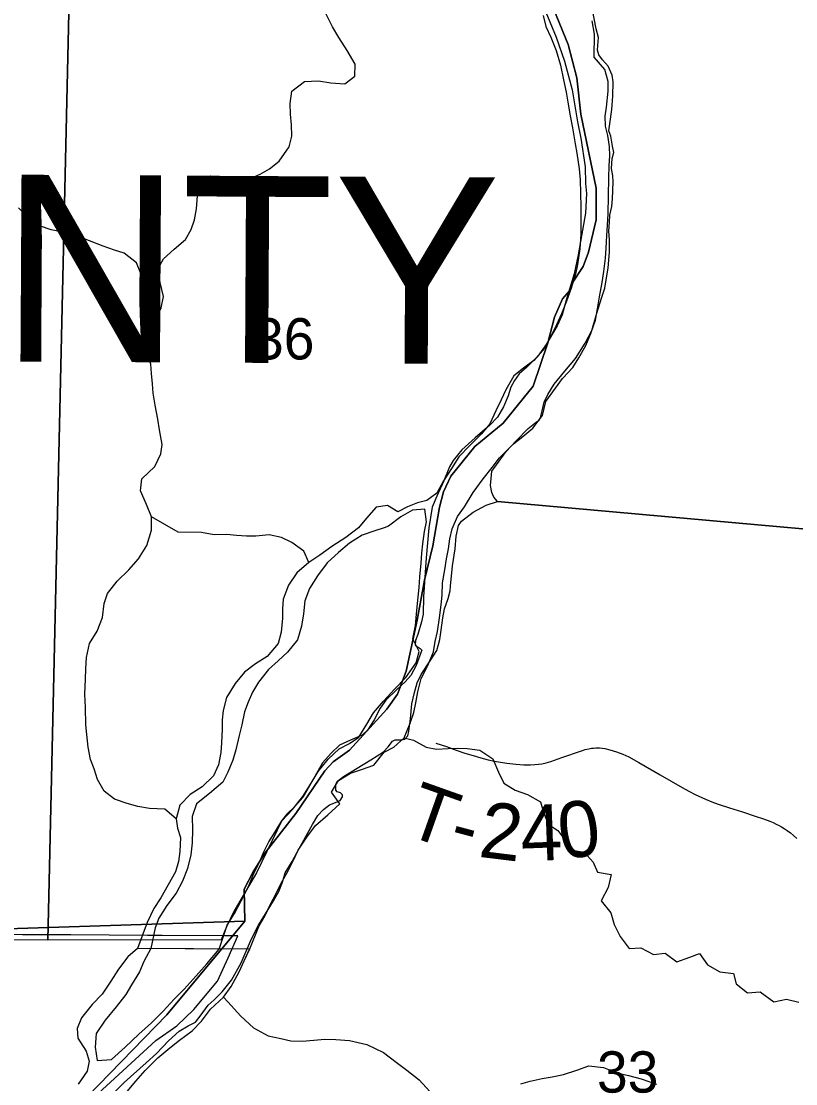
# Model space of a CAD drawing. Extents: x -38.1 to 35.9, y -2.7 to 28.5.
# Drawn here: x 10.189 to 10.974, y 17.716 to 18.793 of the extents above; entities that cross this region are included whole.
import ezdxf

# ---------------------------------------------------------------- set-up
doc = ezdxf.new("R2010")
doc.units = 0
for name, color, linetype in [('GM_X_Major_River_Text', 7, 'Continuous'), ('GM_X_Minor_Lake', 7, 'Continuous'), ('GM_X_Minor_River', 7, 'Continuous'), ('GM_X_Rail_Line', 7, 'Continuous'), ('GM_X_Section', 7, 'Continuous'), ('GM_X_Township_Road', 7, 'Continuous'), ('GM_X_US_Route', 7, 'Continuous')]:
    doc.layers.add(name, color=color, linetype=linetype)

msp = doc.modelspace()

# ---------------------------------------------------------------- linework, layer by layer
at = {"layer": 'GM_X_Major_River_Text'}
msp.add_lwpolyline([(10.6088, 18.0608), (10.6195, 18.0574), (10.6293, 18.0539), (10.6384, 18.0508), (10.6468, 18.0482), (10.6544, 18.0459), (10.662, 18.0441), (10.6684, 18.0427), (10.6745, 18.0415), (10.6807, 18.0405), (10.69, 18.0395), (10.6981, 18.039), (10.7049, 18.039), (10.7092, 18.0392), (10.7129, 18.0395), (10.7163, 18.0399), (10.7206, 18.0409), (10.7253, 18.0423), (10.7365, 18.0462), (10.7564, 18.0532), (10.7603, 18.0545), (10.7638, 18.0552), (10.7668, 18.0558), (10.7688, 18.0559), (10.7709, 18.056), (10.7727, 18.056), (10.7746, 18.056), (10.7774, 18.0557), (10.78, 18.0553), (10.7854, 18.0541), (10.7919, 18.0521), (10.7983, 18.0496), (10.8044, 18.0469), (10.8147, 18.0414), (10.8364, 18.0289), (10.8587, 18.0158), (10.8652, 18.0121), (10.8719, 18.0087), (10.8822, 18.0041), (10.8886, 18.0014), (10.8952, 17.999), (10.9067, 17.9952), (10.9196, 17.9912), (10.9326, 17.987), (10.9409, 17.9842), (10.9474, 17.9818), (10.9507, 17.9804), (10.9538, 17.9789), (10.9568, 17.9774), (10.9594, 17.976), (10.9621, 17.9744), (10.9649, 17.9724), (10.9683, 17.9698), (10.9715, 17.9671), (10.9749, 17.9641)], dxfattribs=at)
at = {"layer": 'GM_X_Section'}
for points in [[(10.3168, 18.4914), (10.3255, 18.4917), (10.3302, 18.5023), (10.3326, 18.5137), (10.3293, 18.5278), (10.3272, 18.5422), (10.3327, 18.552), (10.3434, 18.5618), (10.3549, 18.5715), (10.3607, 18.5817), (10.3642, 18.5916), (10.3663, 18.6025), (10.3672, 18.6158), (10.3693, 18.6287), (10.3803, 18.6362), (10.3924, 18.6341), (10.4053, 18.6306), (10.4174, 18.6319), (10.4308, 18.6379), (10.4403, 18.6431), (10.4499, 18.6509), (10.46, 18.6653), (10.4627, 18.6762), (10.4625, 18.6876), (10.4615, 18.6987), (10.4613, 18.7093), (10.4629, 18.7218), (10.4756, 18.7316), (10.49, 18.7322), (10.5025, 18.7305), (10.5165, 18.7292), (10.5268, 18.737), (10.527, 18.7492), (10.5188, 18.763), (10.5106, 18.7764), (10.5039, 18.7871), (10.4976, 18.8001)], [(10.3455, 17.9843), (10.3342, 17.994), (10.3187, 17.9945), (10.3066, 17.9966), (10.296, 17.9997), (10.2831, 18.0041), (10.2726, 18.0122), (10.2659, 18.024), (10.2623, 18.0347), (10.2586, 18.0443), (10.2565, 18.0568), (10.2551, 18.0697), (10.2541, 18.0796), (10.2535, 18.0971), (10.253, 18.1104), (10.2535, 18.1256), (10.254, 18.1362), (10.2545, 18.1476), (10.2578, 18.162), (10.2655, 18.1744), (10.271, 18.1884), (10.2727, 18.2025), (10.2758, 18.2127), (10.2858, 18.2251), (10.2977, 18.2367), (10.3073, 18.2476), (10.3158, 18.2612), (10.3206, 18.2767), (10.3207, 18.2904), (10.3156, 18.303), (10.3093, 18.3168), (10.3106, 18.3289), (10.324, 18.3413), (10.3299, 18.3541), (10.3315, 18.3636), (10.3286, 18.3784), (10.3269, 18.3895), (10.3244, 18.4036), (10.3223, 18.4158), (10.3216, 18.4253), (10.3206, 18.4355), (10.32, 18.445), (10.3156, 18.4576), (10.3127, 18.4687), (10.3155, 18.4793), (10.3168, 18.4914), (10.3154, 18.5055), (10.3137, 18.5177), (10.3119, 18.5276), (10.3097, 18.5371), (10.3053, 18.5478), (10.2929, 18.5578), (10.2831, 18.5606), (10.2714, 18.5646), (10.2578, 18.57), (10.245, 18.5751), (10.234, 18.5783), (10.2189, 18.5812), (10.2079, 18.5851), (10.1981, 18.5909), (10.1858, 18.6036)], [(10.4802, 18.244), (10.475, 18.2555), (10.463, 18.2644), (10.4525, 18.2694), (10.44, 18.2722), (10.4263, 18.2709), (10.4168, 18.2706), (10.4066, 18.2715), (10.3971, 18.2724), (10.3842, 18.2722), (10.3714, 18.2746), (10.3475, 18.2749), (10.3207, 18.2904)], [(10.5766, 18.0662), (10.5861, 18.0638), (10.5989, 18.0568), (10.6095, 18.0548), (10.6213, 18.0554), (10.6307, 18.0557), (10.6406, 18.0556), (10.6535, 18.0539), (10.6666, 18.045), (10.6722, 18.0316), (10.6777, 18.0202), (10.6894, 18.0132), (10.7018, 18.0089), (10.715, 18.0015), (10.7179, 17.9908), (10.7227, 17.9786), (10.7325, 17.9724), (10.7396, 17.9628), (10.747, 17.9525), (10.7592, 17.9504), (10.7685, 17.9401), (10.7729, 17.9302), (10.7866, 17.9277), (10.7834, 17.9145), (10.7764, 17.9009), (10.7861, 17.889), (10.7897, 17.8772), (10.7957, 17.8649), (10.805, 17.8527), (10.8168, 17.8533), (10.8296, 17.8467), (10.8413, 17.8481), (10.853, 17.8392), (10.8663, 17.844), (10.8762, 17.8476), (10.8844, 17.8362), (10.8969, 17.8292), (10.9105, 17.8275), (10.9134, 17.8168), (10.9247, 17.8076), (10.9376, 17.8086), (10.9515, 17.7985), (10.9644, 17.8014), (10.9769, 17.7982)], [(10.3934, 17.8034), (10.3978, 17.7987), (10.4113, 17.7842), (10.4241, 17.7722), (10.4388, 17.7641), (10.4516, 17.7613), (10.4618, 17.7592), (10.4732, 17.7587), (10.485, 17.7597), (10.4964, 17.7607), (10.5074, 17.7606), (10.5214, 17.7593), (10.5388, 17.7553), (10.5557, 17.7471), (10.5685, 17.7374), (10.5794, 17.7293), (10.5918, 17.7197), (10.6027, 17.7078)], [(10.6949, 17.7154), (10.7044, 17.7183), (10.7166, 17.7209), (10.7268, 17.7226), (10.7382, 17.7251), (10.7519, 17.7292), (10.7638, 17.7339), (10.7789, 17.7319), (10.7925, 17.7268), (10.8042, 17.724), (10.8171, 17.7204), (10.8325, 17.7153)]]:
    msp.add_lwpolyline(points, dxfattribs=at)
at = {"layer": 'GM_X_Township_Road'}
for p, q in [((10.42, 17.8521), (10.3065, 17.8527)), ((10.389, 17.852), (10.3199, 17.8526))]:
    msp.add_line(p, q, dxfattribs=at)
for points in [[(10.7176, 18.7986), (10.7205, 18.7875), (10.7253, 18.7765), (10.7308, 18.7631), (10.7351, 18.7482), (10.7384, 18.7334), (10.7409, 18.7208), (10.7427, 18.7109), (10.7451, 18.6968)], [(10.4201, 17.8523), (10.4295, 17.8751), (10.4357, 17.886), (10.4411, 17.8977), (10.4469, 17.9083), (10.4516, 17.9181), (10.4594, 17.9321), (10.4644, 17.9422), (10.4691, 17.9524), (10.478, 17.9656), (10.4868, 17.9773), (10.4995, 17.9882), (10.5114, 17.9994), (10.5032, 18.0113), (10.5101, 18.023), (10.5224, 18.0304), (10.5334, 18.0341), (10.546, 18.0385), (10.5564, 18.0516), (10.5663, 18.0568), (10.5766, 18.0662), (10.5829, 18.0813), (10.5864, 18.0919), (10.5884, 18.1018), (10.5905, 18.1128), (10.5941, 18.1264), (10.6007, 18.1396), (10.6065, 18.1536), (10.6082, 18.1638), (10.6106, 18.1741), (10.6126, 18.1881), (10.6143, 18.201), (10.6152, 18.2109), (10.6157, 18.2234), (10.6178, 18.2367), (10.6198, 18.2476), (10.6218, 18.2579), (10.6231, 18.2681), (10.6255, 18.2783), (10.6309, 18.2908), (10.6379, 18.3006), (10.6468, 18.3149), (10.6568, 18.3289), (10.6661, 18.3402), (10.6734, 18.35), (10.6876, 18.3642), (10.6972, 18.3717), (10.7071, 18.3803), (10.7171, 18.3931), (10.7203, 18.4071), (10.73, 18.4207), (10.7373, 18.4305), (10.7477, 18.4418), (10.7539, 18.4516), (10.7609, 18.464), (10.7659, 18.4761), (10.7706, 18.4897), (10.7727, 18.5011), (10.7747, 18.5133), (10.7776, 18.528), (10.7792, 18.539), (10.7809, 18.5527), (10.7814, 18.5626), (10.7823, 18.5755), (10.7828, 18.5861), (10.7837, 18.5975), (10.7842, 18.634), (10.7847, 18.6461), (10.7852, 18.6564), (10.785, 18.6659), (10.7832, 18.6769), (10.781, 18.6865), (10.7804, 18.6964), (10.7817, 18.7058), (10.7834, 18.7218), (10.7835, 18.7317), (10.7802, 18.7439), (10.7694, 18.7562), (10.7697, 18.7797), (10.7672, 18.7931)], [(10.7451, 18.6968), (10.7473, 18.6846), (10.7501, 18.6686), (10.7519, 18.6591), (10.754, 18.6431), (10.755, 18.6321), (10.7555, 18.6184), (10.7558, 18.6043), (10.756, 18.5914), (10.7558, 18.5769), (10.7549, 18.5621), (10.7524, 18.5462), (10.7504, 18.5364), (10.746, 18.5223), (10.7413, 18.5091), (10.7362, 18.4962), (10.7312, 18.4849), (10.7265, 18.4751), (10.7191, 18.4615), (10.7083, 18.4487), (10.6976, 18.4412), (10.688, 18.4334), (10.6799, 18.419), (10.6752, 18.4088), (10.6698, 18.3979), (10.6636, 18.3846), (10.6551, 18.3745), (10.6432, 18.3625), (10.6321, 18.3512), (10.6247, 18.3395), (10.6166, 18.3267), (10.61, 18.3142), (10.5997, 18.3068), (10.5902, 18.3046), (10.5802, 18.3006), (10.5703, 18.2954), (10.5598, 18.3019), (10.5484, 18.3002), (10.5384, 18.2889), (10.5303, 18.2791), (10.5177, 18.2694), (10.5035, 18.2604), (10.4913, 18.2515), (10.4802, 18.244), (10.4679, 18.2335), (10.4594, 18.2211), (10.454, 18.2067), (10.4535, 18.1972), (10.4534, 18.1877), (10.452, 18.1733), (10.4489, 18.162), (10.4377, 18.1488), (10.4259, 18.1414), (10.4148, 18.1328), (10.4055, 18.1215), (10.3966, 18.1071), (10.3931, 18.0939), (10.3922, 18.0844), (10.3921, 18.0749), (10.3915, 18.0612), (10.391, 18.0514), (10.3886, 18.0389), (10.3835, 18.0279), (10.372, 18.0167), (10.3598, 18.0088), (10.3494, 17.9979), (10.3455, 17.9843), (10.3469, 17.9748), (10.3498, 17.9653), (10.3492, 17.9509), (10.348, 17.941), (10.3448, 17.9304), (10.3301, 17.904), (10.3228, 17.8931), (10.3161, 17.8791), (10.3064, 17.8527)], [(10.389, 17.852), (10.3973, 17.8762), (10.4046, 17.8883), (10.4116, 17.9011), (10.419, 17.9155), (10.424, 17.9279), (10.4303, 17.9408), (10.4346, 17.9506), (10.4396, 17.9608), (10.4458, 17.971), (10.4528, 17.9823), (10.4635, 17.9935), (10.4739, 18.0067), (10.4824, 18.0203), (10.4894, 18.032), (10.4998, 18.0447), (10.5109, 18.0552), (10.5212, 18.0604), (10.5308, 18.0668), (10.5389, 18.0803), (10.5455, 18.0917), (10.5559, 18.1033), (10.567, 18.1157), (10.5785, 18.1273), (10.5889, 18.1424), (10.5921, 18.1538), (10.5854, 18.1668), (10.5883, 18.18), (10.5892, 18.1918), (10.5905, 18.2058), (10.5918, 18.2187), (10.5927, 18.2294), (10.594, 18.2434), (10.5945, 18.2536), (10.5957, 18.2631), (10.5974, 18.2753), (10.5994, 18.2851), (10.5977, 18.2981), (10.5851, 18.2971), (10.5733, 18.2904), (10.561, 18.281), (10.5565, 18.2792)], [(10.5565, 18.2792), (10.547, 18.2763), (10.534, 18.2719), (10.5214, 18.2637), (10.5103, 18.2543), (10.4988, 18.2438), (10.4888, 18.2306), (10.4806, 18.2178), (10.4759, 18.2053), (10.4746, 18.192), (10.4726, 18.1795), (10.4686, 18.1655), (10.4586, 18.1531), (10.449, 18.1445), (10.4391, 18.1355), (10.4291, 18.1227), (10.4229, 18.1125), (10.4186, 18.1023), (10.415, 18.0925), (10.4122, 18.0796), (10.4094, 18.0686), (10.4062, 18.0542), (10.4031, 18.0436), (10.398, 18.0315), (10.3929, 18.0213), (10.3795, 18.0097), (10.3661, 17.9993), (10.3618, 17.9864), (10.362, 17.9731), (10.3619, 17.9598), (10.3606, 17.9477), (10.357, 17.9337), (10.3519, 17.9208), (10.3457, 17.9087), (10.3361, 17.8963), (10.3279, 17.8835), (10.3244, 17.8737), (10.3199, 17.8526)], [(10.3064, 17.8527), (10.2965, 17.8441), (10.2872, 17.8317), (10.2794, 17.8197), (10.2705, 17.8065), (10.2604, 17.796), (10.2496, 17.7825), (10.2452, 17.7716), (10.2458, 17.7617), (10.2544, 17.7487), (10.2572, 17.7384), (10.2552, 17.7285), (10.2462, 17.715)], [(10.3065, 17.8527), (10.2965, 17.8441), (10.2872, 17.8317), (10.2794, 17.8197), (10.2705, 17.8065), (10.2604, 17.796), (10.2496, 17.7825), (10.2452, 17.7716), (10.2458, 17.7617), (10.2544, 17.7487), (10.2572, 17.7384), (10.2552, 17.7285), (10.2462, 17.715)], [(10.3199, 17.8526), (10.3127, 17.8396), (10.3084, 17.8291), (10.3002, 17.8159), (10.2947, 17.8061), (10.2847, 17.7934), (10.2735, 17.7799), (10.2645, 17.7664), (10.2635, 17.7527), (10.2656, 17.739), (10.28, 17.7403), (10.2939, 17.7526), (10.3078, 17.7657), (10.3205, 17.7772), (10.3324, 17.7892), (10.3436, 17.8015), (10.3537, 17.8116), (10.366, 17.8251), (10.3765, 17.8371), (10.389, 17.852)], [(10.2924, 17.7036), (10.3047, 17.7182), (10.314, 17.7291), (10.3271, 17.7418), (10.3391, 17.7519), (10.349, 17.7597), (10.3617, 17.7693), (10.3714, 17.7791), (10.3803, 17.7911), (10.3934, 17.8034), (10.4012, 17.8143), (10.4094, 17.829), (10.4145, 17.8403), (10.4201, 17.8523)], [(10.2924, 17.7036), (10.3047, 17.7182), (10.314, 17.7291), (10.3271, 17.7418), (10.3391, 17.7519), (10.349, 17.7597), (10.3617, 17.7693), (10.3714, 17.7791), (10.3803, 17.7911), (10.3934, 17.8034), (10.4012, 17.8143), (10.4094, 17.829), (10.4145, 17.8403), (10.42, 17.8521)]]:
    msp.add_lwpolyline(points, dxfattribs=at)
at = {"layer": 'GM_X_US_Route'}
for points in [[(14.9146, 19.7308), (8.1146, 19.7308), (8.1146, 17.8763), (8.2228, 17.8761), (8.7564, 17.8708), (8.7662, 17.8706), (9.0262, 17.8689), (9.5019, 17.8671), (9.8985, 17.8644), (9.9118, 17.8643), (10.4152, 17.8803), (10.3361, 17.7853), (10.2437, 17.6904)], [(10.7203, 18.8019), (10.7308, 18.7767), (10.7394, 18.7523), (10.7472, 18.7234), (10.7523, 18.6907), (10.7557, 18.6743), (10.7601, 18.6451), (10.7606, 18.6284), (10.7615, 18.6182), (10.7604, 18.5981), (10.7565, 18.5751), (10.7532, 18.5559), (10.749, 18.5366), (10.7409, 18.5099), (10.7369, 18.4952), (10.7317, 18.4839), (10.7208, 18.4652), (10.7122, 18.4532), (10.701, 18.4421), (10.6933, 18.4354), (10.6887, 18.4287), (10.6847, 18.4219), (10.6823, 18.4129), (10.6776, 18.402), (10.6713, 18.3915), (10.6636, 18.3833), (10.6486, 18.3703), (10.6351, 18.3581), (10.6265, 18.3473), (10.6226, 18.3409), (10.6171, 18.327), (10.61, 18.3112), (10.6052, 18.3), (10.6018, 18.2792), (10.5989, 18.2486), (10.5963, 18.2092), (10.596, 18.1918), (10.5943, 18.1839), (10.5907, 18.1711), (10.5883, 18.1651), (10.5878, 18.1605), (10.5886, 18.1594), (10.5908, 18.1582), (10.5931, 18.157), (10.5945, 18.1551), (10.5941, 18.1536), (10.5889, 18.1397), (10.5835, 18.1296), (10.5777, 18.1229), (10.5688, 18.1151), (10.558, 18.1043), (10.5525, 18.0964), (10.5463, 18.0844), (10.5396, 18.074), (10.5342, 18.0691), (10.5224, 18.064), (10.5113, 18.059), (10.5028, 18.0508), (10.4939, 18.0411), (10.4849, 18.0246), (10.474, 18.0059), (10.4658, 17.9966), (10.4577, 17.9888), (10.4527, 17.9824), (10.448, 17.9727), (10.4271, 17.9295), (10.4126, 17.9048), (10.404, 17.8902), (10.3965, 17.8748), (10.3913, 17.8614), (10.2156, 17.8613), (10.2384, 18.8764)], [(9.9118, 17.8643), (10.4152, 17.8803), (10.4146, 17.9128), (10.4236, 17.9305), (10.4356, 17.9494), (10.4669, 17.9896), (10.4964, 18.0329), (10.5049, 18.0419), (10.5214, 18.0538), (10.5592, 18.0955), (10.57, 18.1106), (10.5787, 18.134), (10.59, 18.1855), (10.5975, 18.2262), (10.6059, 18.261), (10.6126, 18.3001), (10.6166, 18.3156), (10.6241, 18.3316), (10.6484, 18.3616), (10.6772, 18.3852), (10.7074, 18.4228), (10.7224, 18.4667), (10.7292, 18.4928), (10.7371, 18.5114), (10.7444, 18.5196), (10.7472, 18.5272), (10.7581, 18.5442), (10.7636, 18.5586), (10.7713, 18.5915), (10.7713, 18.6235), (10.7557, 18.6986), (10.7519, 18.7355), (10.743, 18.7692), (10.717, 18.8331)], [(10.717, 18.8331), (10.743, 18.7692), (10.7519, 18.7355), (10.7557, 18.6986), (10.7713, 18.6235), (10.7713, 18.5915), (10.7636, 18.5586), (10.7581, 18.5442), (10.7472, 18.5272), (10.7444, 18.5196), (10.7371, 18.5114), (10.7292, 18.4928), (10.7224, 18.4667), (10.7074, 18.4228), (10.6772, 18.3852), (10.6484, 18.3616), (10.6241, 18.3316), (10.6166, 18.3156), (10.6126, 18.3001), (10.6059, 18.261), (10.5975, 18.2262), (10.59, 18.1855), (10.5787, 18.134), (10.57, 18.1106), (10.5592, 18.0955), (10.5214, 18.0538), (10.5049, 18.0419), (10.4964, 18.0329), (10.4669, 17.9896), (10.4356, 17.9494), (10.4236, 17.9305), (10.4146, 17.9128), (10.4152, 17.8803), (10.3361, 17.7853), (10.2437, 17.6904)], [(11.2671, 18.2524), (10.6712, 18.3059), (10.6675, 18.3102), (10.6657, 18.3151), (10.6643, 18.322), (10.6648, 18.3291), (10.6657, 18.3367), (10.6704, 18.3431), (10.6801, 18.3565), (10.6898, 18.3669), (10.7025, 18.3799), (10.711, 18.3866), (10.7137, 18.3884), (10.7148, 18.3911), (10.7165, 18.3979), (10.7185, 18.4065), (10.7225, 18.4144), (10.7287, 18.4249), (10.7396, 18.4379), (10.7504, 18.451), (10.7602, 18.4663), (10.7669, 18.4791), (10.7721, 18.4968), (10.7769, 18.5119), (10.7802, 18.522), (10.7836, 18.5428), (10.785, 18.5587), (10.7849, 18.5712), (10.7843, 18.5799), (10.7848, 18.589), (10.7853, 18.5962), (10.7874, 18.6048), (10.7879, 18.6128), (10.7886, 18.6298), (10.7884, 18.6359), (10.787, 18.6435), (10.7871, 18.6484), (10.7876, 18.6537), (10.7892, 18.6597), (10.7878, 18.6662), (10.7861, 18.6761), (10.7843, 18.6818), (10.7852, 18.6889), (10.7873, 18.7033), (10.7884, 18.7169), (10.7886, 18.7313), (10.7876, 18.7381), (10.7836, 18.7473), (10.7777, 18.7535), (10.774, 18.7588), (10.7726, 18.7634), (10.773, 18.7683), (10.7736, 18.7763), (10.7715, 18.785), (10.7659, 18.8132)], [(10.2762, 17.7002), (10.2928, 17.7169), (10.3152, 17.7369), (10.3256, 17.7462), (10.3379, 17.7592), (10.3487, 17.7689), (10.3579, 17.7744), (10.3652, 17.778), (10.3698, 17.784), (10.378, 17.7952), (10.3842, 17.8008), (10.3922, 17.8086), (10.4016, 17.8205), (10.4114, 17.8381), (10.422, 17.8626), (10.4291, 17.8764), (10.4389, 17.8922), (10.4444, 17.9011), (10.4495, 17.9105), (10.4534, 17.9199), (10.4562, 17.9293), (10.4633, 17.9409), (10.4684, 17.9503), (10.4837, 17.9784), (10.4891, 17.9874), (10.4949, 17.9937), (10.5011, 17.9985), (10.5072, 18.0007), (10.5118, 18.0029), (10.5141, 18.0063), (10.5142, 18.0085), (10.5123, 18.0105), (10.5089, 18.0117), (10.5074, 18.0132), (10.5075, 18.0158), (10.5075, 18.0193), (10.5091, 18.0223), (10.5153, 18.0271), (10.5428, 18.044), (10.5559, 18.0521), (10.5605, 18.0573), (10.5648, 18.0629), (10.5675, 18.0643), (10.5709, 18.0643), (10.5743, 18.0642), (10.5773, 18.0649), (10.5804, 18.0683), (10.5816, 18.0732), (10.583, 18.0856), (10.5844, 18.1008), (10.5873, 18.1124), (10.5898, 18.1222), (10.5941, 18.1305), (10.603, 18.1443), (10.6097, 18.1548), (10.6117, 18.1608), (10.6129, 18.1661), (10.6142, 18.1756), (10.616, 18.188), (10.6177, 18.1971), (10.6213, 18.2076), (10.6233, 18.2152), (10.6238, 18.2201), (10.6257, 18.2405), (10.6283, 18.2579), (10.6296, 18.2707), (10.6317, 18.2817), (10.6349, 18.2858), (10.6468, 18.295), (10.6598, 18.302), (10.6712, 18.3059), (11.2671, 18.2524)], [(10.2437, 17.6904), (10.3361, 17.7853), (10.4152, 17.8803), (9.9118, 17.8643), (9.8985, 17.8644), (9.5019, 17.8671), (9.0262, 17.8689), (8.7662, 17.8706), (8.7564, 17.8708), (8.2228, 17.8761), (8.1146, 17.8763), (8.1146, 12.9308)], [(10.2437, 17.6904), (10.3361, 17.7853), (10.4152, 17.8803), (9.9118, 17.8643), (9.8985, 17.8644), (9.5019, 17.8671), (9.0262, 17.8689), (8.7662, 17.8706), (8.7564, 17.8708), (8.2228, 17.8761), (8.1146, 17.8763), (8.1146, 12.9308)], [(10.2665, 17.7058), (10.3248, 17.7595), (10.3464, 17.7744), (10.3635, 17.7907), (10.3876, 17.8196), (10.3983, 17.8433), (10.4082, 17.8654), (10.3978, 17.8655), (10.3945, 17.8655), (10.3313, 17.8659), (10.3166, 17.8659), (10.2388, 17.8664), (10.1899, 17.8666), (10.0127, 17.8675), (10.0078, 17.8675), (9.9172, 17.8679), (9.9128, 17.8679), (9.9085, 17.8679), (9.9064, 17.8679), (9.9048, 17.861), (9.867, 17.7024)]]:
    msp.add_lwpolyline(points, dxfattribs=at)
msp.add_lwpolyline([(9.2246, 18.878), (10.2384, 18.8764), (10.2156, 17.8613), (9.2136, 17.8669)], close=True, dxfattribs=at)

# ---------------------------------------------------------------- texts
at = {"layer": 'GM_X_Minor_Lake'}
for s, rotation, p in [('T', 340.4828, (10.5753, 17.9691)), ('2', 353.0322, (10.6511, 17.9458)), ('0', 7.5582, (10.7365, 17.9429)), ('4', 2.097, (10.6956, 17.9411)), ('-', 345.0599, (10.6201, 17.9534))]:
    msp.add_text(s, height=0.0568, rotation=rotation, dxfattribs=at).set_placement(p)
at = {"layer": 'GM_X_Minor_River'}
for s, p in [('36', (10.4235, 18.4499)), ('33', (10.7722, 17.7066))]:
    msp.add_text(s, height=0.04186, rotation=0, dxfattribs=at).set_placement(p)
at = {"layer": 'GM_X_Rail_Line'}
msp.add_text('MIAMI COUNTY', height=0.189394, rotation=359.6735, dxfattribs=at).set_placement((8.8022, 18.4557))

doc.saveas('drawing.dxf')
